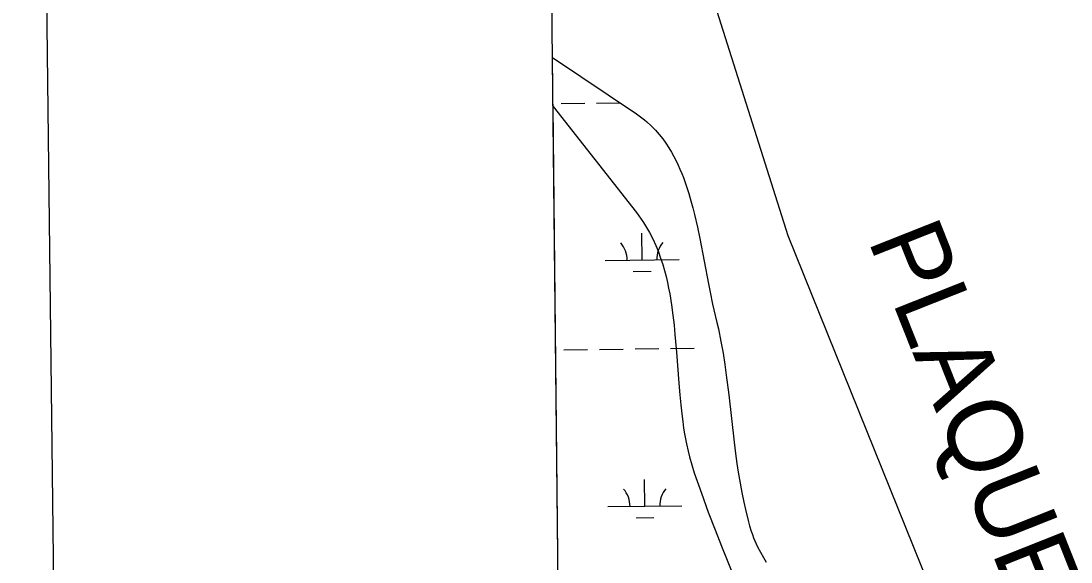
# Model space of a CAD drawing. Extents: x 3678539 to 3716648, y 451386 to 477139.
# Drawn here: x 3681880 to 3683298, y 471768 to 472499 of the extents above; entities that cross this region are included whole.
import ezdxf

# ---------------------------------------------------------------- set-up
doc = ezdxf.new("R2010")
doc.units = 0
for name, color, linetype in [('V-ANNO-SYMB', 7, 'Continuous'), ('V-GRID-FRAM', 7, 'Continuous'), ('V-SITE-VEGE', 7, 'Continuous'), ('V-TOPO-BNDY', 7, 'Continuous'), ('V-TOPO-GNAM-IDEN', 7, 'Continuous'), ('V-TOPO-SHOR', 7, 'Continuous'), ('V-WETL-SWMP', 7, 'Continuous')]:
    doc.layers.add(name, color=color, linetype=linetype)

msp = doc.modelspace()

# ---------------------------------------------------------------- linework, layer by layer
at = {"layer": 'V-ANNO-SYMB'}
msp.add_lwpolyline([(3682143.1, 452625.9), (3715224.1, 453006), (3714960.8, 475921.1), (3681879.8, 475540.9), (3682143.1, 452625.9)], dxfattribs=at)
at = {"layer": 'V-GRID-FRAM'}
msp.add_lwpolyline([(3682569.5, 474981.5), (3714284.1, 475345.9), (3714501, 457164.6), (3682770.5, 456800), (3682569.5, 474981.5)], dxfattribs=at)
at = {"layer": 'V-SITE-VEGE'}
for p, q in [((3682646.4, 468024.3), (3682598.3, 472383.5)), ((3682598.3, 472383.5), (3682710.9, 472240.3)), ((3682710.9, 472240.3), (3682714.3, 472235.8)), ((3682714.3, 472235.8), (3682717.4, 472231.4)), ((3682717.4, 472231.4), (3682720.5, 472226.9)), ((3682720.5, 472226.9), (3682723.3, 472222.5)), ((3682723.3, 472222.5), (3682725.9, 472218)), ((3682725.9, 472218), (3682728.4, 472213.6)), ((3682728.4, 472213.6), (3682733, 472204.7)), ((3682733, 472204.7), (3682737, 472195.9)), ((3682737, 472195.9), (3682740.5, 472187.3)), ((3682740.5, 472187.3), (3682743.6, 472178.7)), ((3682743.6, 472178.7), (3682746.4, 472170.3)), ((3682746.4, 472170.3), (3682748.8, 472162.1)), ((3682748.8, 472162.1), (3682750.9, 472154)), ((3682750.9, 472154), (3682752.7, 472146)), ((3682752.7, 472146), (3682754.4, 472138.3)), ((3682754.4, 472138.3), (3682755.8, 472130.7)), ((3682755.8, 472130.7), (3682758.3, 472115.8)), ((3682758.3, 472115.8), (3682760.2, 472101.7)), ((3682760.2, 472101.7), (3682761.7, 472088.3)), ((3682761.7, 472088.3), (3682762.9, 472075.7)), ((3682762.9, 472075.7), (3682764.9, 472051.8)), ((3682764.9, 472051.8), (3682768.1, 472009.9)), ((3682768.1, 472009.9), (3682769.4, 471994.2)), ((3682769.4, 471994.2), (3682770.7, 471980.5)), ((3682770.7, 471980.5), (3682772.1, 471968.6)), ((3682772.1, 471968.6), (3682773.4, 471958.3)), ((3682773.4, 471958.3), (3682774.7, 471949.3)), ((3682774.7, 471949.3), (3682776, 471941.5)), ((3682776, 471941.5), (3682778.5, 471928)), ((3682778.5, 471928), (3682780.7, 471917.9)), ((3682780.7, 471917.9), (3682782.5, 471910.5)), ((3682782.5, 471910.5), (3682785.6, 471899.5)), ((3682785.6, 471899.5), (3682789.1, 471888.6)), ((3682789.1, 471888.6), (3682798.6, 471861.3)), ((3682798.6, 471861.3), (3682808, 471835.8)), ((3682808, 471835.8), (3682817.1, 471811.9)), ((3682817.1, 471811.9), (3682825.9, 471789.6)), ((3682825.9, 471789.6), (3682834.3, 471768.7)), ((3682834.3, 471768.7), (3682850.4, 471729.6))]:
    msp.add_line(p, q, dxfattribs=at)
at = {"layer": 'V-TOPO-BNDY'}
for p, q in [((3682687.8, 472930.6), (3682915.2, 472209.5)), ((3682915.2, 472209.5), (3683265.3, 471341.7))]:
    msp.add_line(p, q, dxfattribs=at)
at = {"layer": 'V-TOPO-SHOR'}
for p, q in [((3682597.5, 472449.7), (3682710.9, 472373.7)), ((3682710.9, 472373.7), (3682714.6, 472371.1)), ((3682714.6, 472371.1), (3682718.2, 472368.5)), ((3682718.2, 472368.5), (3682721.6, 472365.8)), ((3682721.6, 472365.8), (3682724.9, 472363)), ((3682724.9, 472363), (3682731, 472357.4)), ((3682731, 472357.4), (3682736.6, 472351.6)), ((3682736.6, 472351.6), (3682741.7, 472345.7)), ((3682741.7, 472345.7), (3682746.4, 472339.8)), ((3682746.4, 472339.8), (3682750.6, 472333.9)), ((3682750.6, 472333.9), (3682754.5, 472327.9)), ((3682754.5, 472327.9), (3682758.1, 472322)), ((3682758.1, 472322), (3682761.4, 472316.1)), ((3682761.4, 472316.1), (3682764.4, 472310.3)), ((3682764.4, 472310.3), (3682767.2, 472304.5)), ((3682767.2, 472304.5), (3682769.7, 472298.8)), ((3682769.7, 472298.8), (3682772.1, 472293.1)), ((3682772.1, 472293.1), (3682774.3, 472287.6)), ((3682774.3, 472287.6), (3682778.2, 472276.7)), ((3682778.2, 472276.7), (3682781.6, 472266.2)), ((3682781.6, 472266.2), (3682784.6, 472256.2)), ((3682784.6, 472256.2), (3682787.2, 472246.7)), ((3682787.2, 472246.7), (3682789.4, 472237.6)), ((3682789.4, 472237.6), (3682793.3, 472220.5)), ((3682793.3, 472220.5), (3682796.5, 472205.3)), ((3682796.5, 472205.3), (3682808.1, 472143.9)), ((3682808.1, 472143.9), (3682810.3, 472133)), ((3682810.3, 472133), (3682813.8, 472116.8)), ((3682813.8, 472116.8), (3682815.6, 472108.8)), ((3682815.6, 472108.8), (3682819.7, 472092)), ((3682819.7, 472092), (3682821.7, 472083.3)), ((3682821.7, 472083.3), (3682825.1, 472066.3)), ((3682825.1, 472066.3), (3682828, 472050.2)), ((3682828, 472050.2), (3682830.3, 472035.1)), ((3682830.3, 472035.1), (3682832.3, 472020.9)), ((3682832.3, 472020.9), (3682835.7, 471994.3)), ((3682835.7, 471994.3), (3682843, 471930)), ((3682843, 471930), (3682844.9, 471914.8)), ((3682844.9, 471914.8), (3682846.7, 471901.4)), ((3682846.7, 471901.4), (3682848.5, 471889.8)), ((3682848.5, 471889.8), (3682850.1, 471879.7)), ((3682850.1, 471879.7), (3682853.3, 471862.1)), ((3682853.3, 471862.1), (3682855.9, 471849)), ((3682855.9, 471849), (3682858.2, 471839.2)), ((3682858.2, 471839.2), (3682861.8, 471824.6)), ((3682861.8, 471824.6), (3682863.8, 471817.3)), ((3682863.8, 471817.3), (3682866, 471810.1)), ((3682866, 471810.1), (3682867.5, 471805.5)), ((3682867.5, 471805.5), (3682869.1, 471801.1)), ((3682869.1, 471801.1), (3682870.8, 471796.9)), ((3682870.8, 471796.9), (3682874.5, 471788.8)), ((3682874.5, 471788.8), (3682878.4, 471781.4)), ((3682878.4, 471781.4), (3682882.3, 471774.6)), ((3682882.3, 471774.6), (3682886.1, 471768.3))]:
    msp.add_line(p, q, dxfattribs=at)
at = {"layer": 'V-WETL-SWMP'}
for p, q in [((3682647.2, 467956.8), (3682597.5, 472449.7)), ((3682597.5, 472449.7), (3682710.9, 472373.7)), ((3682609.2, 472387.6), (3682641.2, 472388)), ((3682657.2, 472388.2), (3682688.7, 472388.6)), ((3682710.9, 472373.7), (3682714.6, 472371.1)), ((3682714.6, 472371.1), (3682718.2, 472368.5)), ((3682718.2, 472368.5), (3682721.6, 472365.8)), ((3682721.6, 472365.8), (3682724.9, 472363)), ((3682724.9, 472363), (3682731, 472357.4)), ((3682731, 472357.4), (3682736.6, 472351.6)), ((3682736.6, 472351.6), (3682741.7, 472345.7)), ((3682741.7, 472345.7), (3682746.4, 472339.8)), ((3682746.4, 472339.8), (3682750.6, 472333.9)), ((3682750.6, 472333.9), (3682754.5, 472327.9)), ((3682754.5, 472327.9), (3682758.1, 472322)), ((3682758.1, 472322), (3682761.4, 472316.1)), ((3682761.4, 472316.1), (3682764.4, 472310.3)), ((3682764.4, 472310.3), (3682767.2, 472304.5)), ((3682767.2, 472304.5), (3682769.7, 472298.8)), ((3682769.7, 472298.8), (3682772.1, 472293.1)), ((3682772.1, 472293.1), (3682774.3, 472287.6)), ((3682774.3, 472287.6), (3682778.2, 472276.7)), ((3682778.2, 472276.7), (3682781.6, 472266.2)), ((3682781.6, 472266.2), (3682784.6, 472256.2)), ((3682784.6, 472256.2), (3682787.2, 472246.7)), ((3682787.2, 472246.7), (3682789.4, 472237.6)), ((3682789.4, 472237.6), (3682793.3, 472220.5)), ((3682718.5, 472176.3), (3682718.1, 472212.3)), ((3682793.3, 472220.5), (3682796.5, 472205.3)), ((3682796.5, 472205.3), (3682808.1, 472143.9)), ((3682668.5, 472175.7), (3682768.5, 472176.9)), ((3682706.7, 472160.7), (3682730.7, 472161)), ((3682808.1, 472143.9), (3682810.3, 472133)), ((3682810.3, 472133), (3682813.8, 472116.8)), ((3682813.8, 472116.8), (3682815.6, 472108.8)), ((3682815.6, 472108.8), (3682819.7, 472092)), ((3682819.7, 472092), (3682821.7, 472083.3)), ((3682821.7, 472083.3), (3682825.1, 472066.3)), ((3682825.1, 472066.3), (3682828, 472050.2)), ((3682613, 472055), (3682645, 472055.4)), ((3682661, 472055.5), (3682693, 472055.9)), ((3682709, 472056.1), (3682741, 472056.5)), ((3682757, 472056.6), (3682789, 472057)), ((3682828, 472050.2), (3682830.3, 472035.1)), ((3682830.3, 472035.1), (3682832.3, 472020.9)), ((3682832.3, 472020.9), (3682835.7, 471994.3)), ((3682835.7, 471994.3), (3682843, 471930)), ((3682843, 471930), (3682844.9, 471914.8)), ((3682844.9, 471914.8), (3682846.7, 471901.4)), ((3682846.7, 471901.4), (3682848.5, 471889.8)), ((3682848.5, 471889.8), (3682850.1, 471879.7)), ((3682722.3, 471843.6), (3682721.9, 471879.6)), ((3682850.1, 471879.7), (3682853.3, 471862.1)), ((3682853.3, 471862.1), (3682855.9, 471849)), ((3682672.3, 471843.1), (3682772.3, 471844.2)), ((3682855.9, 471849), (3682858.2, 471839.2)), ((3682710.5, 471828.1), (3682734.5, 471828.3)), ((3682858.2, 471839.2), (3682861.8, 471824.6)), ((3682861.8, 471824.6), (3682863.8, 471817.3)), ((3682863.8, 471817.3), (3682866, 471810.1)), ((3682866, 471810.1), (3682867.5, 471805.5)), ((3682867.5, 471805.5), (3682869.1, 471801.1)), ((3682869.1, 471801.1), (3682870.8, 471796.9)), ((3682870.8, 471796.9), (3682874.5, 471788.8)), ((3682874.5, 471788.8), (3682878.4, 471781.4)), ((3682878.4, 471781.4), (3682882.3, 471774.6)), ((3682882.3, 471774.6), (3682886.1, 471768.3))]:
    msp.add_line(p, q, dxfattribs=at)
for centre, start, end in [((3682663.3, 472176.1), 359.8865, 41.4302), ((3682773.7, 472177.4), 139.8865, 181.4302), ((3682667.1, 471843.5), 359.8865, 41.4302), ((3682777.6, 471844.7), 139.8865, 181.4302)]:
    msp.add_arc(centre, 35.2, start, end, dxfattribs=at)

# ---------------------------------------------------------------- texts
at = {"layer": 'V-TOPO-GNAM-IDEN'}
msp.add_text('PLAQUEMINES', height=100, rotation=291.6367, dxfattribs=at).set_placement((3683023, 472203.6))

doc.saveas('drawing.dxf')
